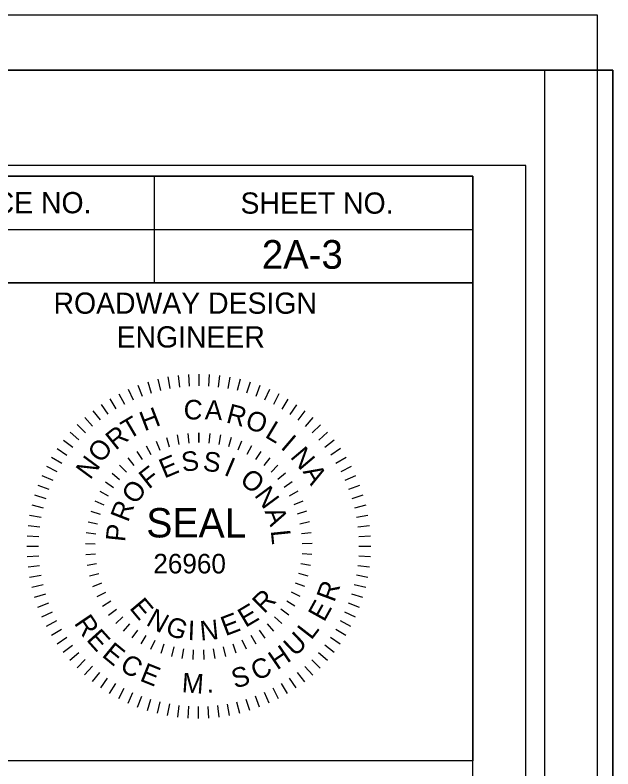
# Model space of a CAD drawing. Extents: x 2294455 to 2294795, y 719276 to 719941.
# Drawn here: x 2294766.36 to 2294794.52, y 719683.27 to 719718.76 of the extents above; entities that cross this region are included whole.
import ezdxf

# ---------------------------------------------------------------- set-up
doc = ezdxf.new("R2010")
doc.units = 0
for name, color, linetype in [('Default', 7, 'Continuous'), ('Old_Level_1', 7, 'Continuous'), ('Old_Level_2', 7, 'Continuous'), ('Sheet Data Field CELL', 7, 'Continuous'), ('Sheet Plan CELL', 7, 'Continuous'), ('Sheet Plot Border Inside CELL', 7, 'Continuous'), ('Sheet Plot Border Outside CELL', 7, 'Continuous'), ('Sheet Typical CELL', 7, 'Continuous')]:
    doc.layers.add(name, color=color, linetype=linetype)

msp = doc.modelspace()

# ---------------------------------------------------------------- linework, layer by layer
at = {"layer": 'Default'}
for p, q in [((2294773.086, 719701.621), (2294773.216, 719701.084)), ((2294773.564, 719701.723), (2294773.662, 719701.18)), ((2294774.047, 719701.796), (2294774.113, 719701.248)), ((2294774.534, 719701.839), (2294774.567, 719701.289)), ((2294775.024, 719701.854), (2294775.023, 719701.302)), ((2294775.513, 719701.839), (2294775.48, 719701.288)), ((2294776, 719701.794), (2294775.934, 719701.246)), ((2294776.484, 719701.72), (2294776.384, 719701.177)), ((2294776.962, 719701.617), (2294776.83, 719701.081)), ((2294772.151, 719701.331), (2294772.347, 719700.814)), ((2294772.613, 719701.49), (2294772.777, 719700.962)), ((2294777.434, 719701.485), (2294777.269, 719700.957)), ((2294777.896, 719701.325), (2294777.699, 719700.809)), ((2294771.259, 719700.93), (2294771.515, 719700.44)), ((2294771.699, 719701.143), (2294771.925, 719700.64)), ((2294778.347, 719701.137), (2294778.121, 719700.634)), ((2294778.787, 719700.923), (2294778.53, 719700.434)), ((2294770.832, 719700.69), (2294771.118, 719700.217)), ((2294779.214, 719700.682), (2294778.927, 719700.21)), ((2294770.027, 719700.135), (2294770.367, 719699.7)), ((2294770.421, 719700.424), (2294770.734, 719699.97)), ((2294779.624, 719700.416), (2294779.31, 719699.962)), ((2294780.017, 719700.126), (2294779.677, 719699.691)), ((2294769.651, 719699.822), (2294770.016, 719699.408)), ((2294780.393, 719699.812), (2294780.027, 719699.399)), ((2294769.294, 719699.487), (2294769.684, 719699.096)), ((2294780.749, 719699.476), (2294780.359, 719699.086)), ((2294768.959, 719699.131), (2294769.371, 719698.764)), ((2294774.506, 719699.068), (2294774.55, 719698.61)), ((2294775.021, 719699.092), (2294775.021, 719698.633)), ((2294775.021, 719698.633), (2294775.021, 719699.092)), ((2294775.537, 719699.067), (2294775.492, 719698.609)), ((2294781.084, 719699.12), (2294780.671, 719698.754)), ((2294768.645, 719698.755), (2294769.079, 719698.415)), ((2294773.008, 719698.701), (2294773.181, 719698.274)), ((2294773.495, 719698.871), (2294773.626, 719698.43)), ((2294773.996, 719698.994), (2294774.083, 719698.542)), ((2294776.047, 719698.992), (2294775.958, 719698.541)), ((2294776.547, 719698.868), (2294776.416, 719698.427)), ((2294777.034, 719698.697), (2294776.86, 719698.27)), ((2294781.397, 719698.743), (2294780.962, 719698.404)), ((2294768.354, 719698.362), (2294768.808, 719698.048)), ((2294772.54, 719698.483), (2294772.753, 719698.076)), ((2294777.502, 719698.479), (2294777.288, 719698.072)), ((2294781.687, 719698.349), (2294781.233, 719698.036)), ((2294772.095, 719698.222), (2294772.346, 719697.837)), ((2294777.946, 719698.217), (2294777.694, 719697.832)), ((2294768.088, 719697.951), (2294768.56, 719697.664)), ((2294771.677, 719697.919), (2294771.965, 719697.56)), ((2294778.364, 719697.913), (2294778.075, 719697.554)), ((2294781.952, 719697.938), (2294781.48, 719697.653)), ((2294767.847, 719697.525), (2294768.336, 719697.268)), ((2294771.291, 719697.577), (2294771.612, 719697.248)), ((2294778.749, 719697.571), (2294778.427, 719697.241)), ((2294782.192, 719697.512), (2294781.703, 719697.255)), ((2294767.633, 719697.085), (2294768.136, 719696.858)), ((2294770.939, 719697.2), (2294771.29, 719696.903)), ((2294779.1, 719697.193), (2294778.748, 719696.896)), ((2294782.405, 719697.071), (2294781.902, 719696.846)), ((2294767.445, 719696.633), (2294767.961, 719696.437)), ((2294770.625, 719696.791), (2294771.004, 719696.528)), ((2294779.413, 719696.783), (2294779.034, 719696.521)), ((2294782.593, 719696.619), (2294782.076, 719696.423)), ((2294770.353, 719696.353), (2294770.755, 719696.128)), ((2294779.684, 719696.345), (2294779.282, 719696.12)), ((2294767.285, 719696.171), (2294767.813, 719696.007)), ((2294770.124, 719695.89), (2294770.546, 719695.706)), ((2294779.913, 719695.881), (2294779.491, 719695.698)), ((2294782.752, 719696.157), (2294782.224, 719695.993)), ((2294767.153, 719695.699), (2294767.689, 719695.568)), ((2294782.883, 719695.685), (2294782.347, 719695.554)), ((2294767.05, 719695.221), (2294767.593, 719695.122)), ((2294769.941, 719695.408), (2294770.379, 719695.266)), ((2294780.095, 719695.399), (2294779.657, 719695.258)), ((2294782.985, 719695.207), (2294782.442, 719695.108)), ((2294769.805, 719694.911), (2294770.254, 719694.811)), ((2294780.23, 719694.901), (2294779.781, 719694.802)), ((2294766.977, 719694.738), (2294767.524, 719694.671)), ((2294783.058, 719694.723), (2294782.51, 719694.657)), ((2294766.932, 719694.251), (2294767.483, 719694.217)), ((2294769.717, 719694.402), (2294770.174, 719694.347)), ((2294780.317, 719694.392), (2294779.86, 719694.338)), ((2294783.102, 719694.236), (2294782.551, 719694.203)), ((2294766.916, 719693.761), (2294767.468, 719693.761)), ((2294769.679, 719693.888), (2294770.139, 719693.876)), ((2294780.354, 719693.878), (2294779.894, 719693.867)), ((2294783.116, 719693.746), (2294782.564, 719693.747)), ((2294769.691, 719693.372), (2294770.15, 719693.405)), ((2294780.341, 719693.362), (2294779.882, 719693.396)), ((2294766.931, 719693.272), (2294767.482, 719693.305)), ((2294783.101, 719693.257), (2294782.55, 719693.291)), ((2294766.975, 719692.785), (2294767.522, 719692.851)), ((2294769.754, 719692.86), (2294770.206, 719692.937)), ((2294779.827, 719692.944), (2294780.281, 719692.867)), ((2294783.056, 719692.77), (2294782.509, 719692.837)), ((2294767.047, 719692.301), (2294767.59, 719692.4)), ((2294769.864, 719692.356), (2294770.308, 719692.476)), ((2294780.166, 719692.346), (2294779.723, 719692.467)), ((2294782.983, 719692.286), (2294782.44, 719692.386)), ((2294767.15, 719691.823), (2294767.686, 719691.954)), ((2294770.023, 719691.865), (2294770.453, 719692.028)), ((2294780.006, 719691.856), (2294779.576, 719692.019)), ((2294782.88, 719691.809), (2294782.344, 719691.94)), ((2294770.229, 719691.393), (2294770.641, 719691.596)), ((2294779.799, 719691.384), (2294779.388, 719691.588)), ((2294767.28, 719691.351), (2294767.809, 719691.515)), ((2294782.748, 719691.336), (2294782.22, 719691.501)), ((2294767.44, 719690.889), (2294767.956, 719691.084)), ((2294770.478, 719690.942), (2294770.87, 719691.183)), ((2294779.549, 719690.933), (2294779.158, 719691.176)), ((2294782.588, 719690.875), (2294782.071, 719691.071)), ((2294767.627, 719690.437), (2294768.131, 719690.662)), ((2294770.771, 719690.516), (2294771.138, 719690.795)), ((2294779.256, 719690.508), (2294778.89, 719690.788)), ((2294782.399, 719690.423), (2294781.896, 719690.649)), ((2294767.84, 719689.996), (2294768.33, 719690.252)), ((2294771.104, 719690.122), (2294771.441, 719690.434)), ((2294778.922, 719690.115), (2294778.586, 719690.428)), ((2294782.185, 719689.983), (2294781.696, 719690.24)), ((2294768.081, 719689.569), (2294768.553, 719689.855)), ((2294771.472, 719689.761), (2294771.778, 719690.106)), ((2294771.874, 719689.438), (2294772.145, 719689.81)), ((2294778.553, 719689.755), (2294778.248, 719690.1)), ((2294781.944, 719689.557), (2294781.472, 719689.843)), ((2294768.346, 719689.159), (2294768.8, 719689.472)), ((2294772.305, 719689.155), (2294772.539, 719689.552)), ((2294777.719, 719689.15), (2294777.485, 719689.547)), ((2294778.15, 719689.432), (2294777.88, 719689.804)), ((2294781.678, 719689.146), (2294781.224, 719689.46)), ((2294768.635, 719688.765), (2294769.07, 719689.104)), ((2294772.762, 719688.915), (2294772.957, 719689.332)), ((2294773.24, 719688.719), (2294773.393, 719689.154)), ((2294776.783, 719688.716), (2294776.631, 719689.151)), ((2294777.261, 719688.911), (2294777.068, 719689.328)), ((2294768.949, 719688.388), (2294769.362, 719688.754)), ((2294773.842, 719689.019), (2294773.731, 719688.572)), ((2294774.24, 719688.472), (2294774.307, 719688.927)), ((2294774.754, 719688.421), (2294774.776, 719688.881)), ((2294775.269, 719688.421), (2294775.248, 719688.881)), ((2294775.783, 719688.471), (2294775.717, 719688.926)), ((2294776.289, 719688.569), (2294776.179, 719689.017)), ((2294781.074, 719688.377), (2294780.662, 719688.743)), ((2294781.388, 719688.753), (2294780.954, 719689.093)), ((2294769.284, 719688.032), (2294769.674, 719688.422)), ((2294780.738, 719688.021), (2294780.349, 719688.412)), ((2294769.639, 719687.696), (2294770.006, 719688.109)), ((2294780.382, 719687.686), (2294780.016, 719688.099)), ((2294770.015, 719687.382), (2294770.356, 719687.816)), ((2294780.006, 719687.373), (2294779.666, 719687.808)), ((2294770.409, 719687.092), (2294770.723, 719687.546)), ((2294779.612, 719687.084), (2294779.298, 719687.538)), ((2294770.819, 719686.826), (2294771.106, 719687.298)), ((2294771.245, 719686.585), (2294771.503, 719687.074)), ((2294778.774, 719686.578), (2294778.518, 719687.067)), ((2294779.201, 719686.818), (2294778.915, 719687.291)), ((2294771.686, 719686.371), (2294771.912, 719686.874)), ((2294772.137, 719686.182), (2294772.334, 719686.699)), ((2294777.882, 719686.177), (2294777.686, 719686.694)), ((2294778.333, 719686.365), (2294778.108, 719686.868)), ((2294772.599, 719686.022), (2294772.764, 719686.55)), ((2294773.071, 719685.891), (2294773.203, 719686.427)), ((2294773.549, 719685.788), (2294773.649, 719686.33)), ((2294774.032, 719685.714), (2294774.099, 719686.262)), ((2294775.985, 719685.712), (2294775.92, 719686.26)), ((2294776.469, 719685.785), (2294776.37, 719686.328)), ((2294776.947, 719685.887), (2294776.816, 719686.423)), ((2294777.419, 719686.018), (2294777.256, 719686.546)), ((2294774.52, 719685.669), (2294774.553, 719686.22)), ((2294775.009, 719685.654), (2294775.009, 719686.206)), ((2294775.498, 719685.668), (2294775.466, 719686.219))]:
    msp.add_line(p, q, dxfattribs=at)
msp.add_lwpolyline([(2294454.524, 719716.169), (2294794.524, 719716.169), (2294794.524, 719496.169), (2294454.524, 719496.169)], close=True, dxfattribs=at)
at = {"layer": 'Old_Level_1'}
msp.add_lwpolyline([(2294747.917, 719676.44), (2294787.924, 719676.44), (2294787.924, 719683.659), (2294747.917, 719683.659)], close=True, dxfattribs=at)
at = {"layer": 'Old_Level_2'}
for p, q in [((2294454.524, 719716.169), (2294794.524, 719716.169)), ((2294794.524, 719716.169), (2294794.524, 719496.169))]:
    msp.add_line(p, q, dxfattribs=at)
at = {"layer": 'Sheet Plan CELL'}
msp.add_lwpolyline([(2294787.924, 719683.659), (2294761.64, 719683.659), (2294761.64, 719706.159), (2294787.924, 719706.159)], dxfattribs=at)
at = {"layer": 'Sheet Plot Border Inside CELL'}
msp.add_lwpolyline([(2294790.424, 719711.679), (2294457.124, 719711.679), (2294457.124, 719500.659), (2294790.424, 719500.659)], close=True, dxfattribs=at)
at = {"layer": 'Sheet Plot Border Outside CELL'}
for points in [[(2294793.79, 719718.758), (2294456.99, 719718.758), (2294456.99, 719498.758), (2294793.79, 719498.758)], [(2294454.524, 719496.169), (2294791.324, 719496.169), (2294791.324, 719716.169), (2294454.524, 719716.169)], [(2294794.524, 719716.169), (2294454.524, 719716.169), (2294454.524, 719496.169), (2294794.524, 719496.169)]]:
    msp.add_lwpolyline(points, close=True, dxfattribs=at)
at = {"layer": 'Sheet Typical CELL'}
for p, q in [((2294772.924, 719711.159), (2294772.924, 719706.159)), ((2294747.914, 719708.659), (2294787.924, 719708.659))]:
    msp.add_line(p, q, dxfattribs=at)
for points in [[(2294787.924, 719711.169), (2294487.924, 719711.169), (2294487.924, 719501.169), (2294787.924, 719501.169)], [(2294747.914, 719711.169), (2294787.924, 719711.169), (2294787.924, 719706.159), (2294747.914, 719706.159)], [(2294787.924, 719706.159), (2294787.924, 719706.159), (2294787.924, 719683.659), (2294787.924, 719683.659)]]:
    msp.add_lwpolyline(points, close=True, dxfattribs=at)

# ---------------------------------------------------------------- texts
at = {"layer": 'Default'}
for s, height, rotation, p in [('C', 0.919, 357.3039, (2294774.286, 719699.747)), ('A', 0.919, 357.3039, (2294775.291, 719699.727)), ('R', 0.919, 345.2946, (2294776.265, 719699.591)), ('H', 0.919, 21.0146, (2294772.456, 719699.157)), ('O', 0.919, 342.2378, (2294777.156, 719699.325)), ('T', 0.919, 30.4466, (2294771.715, 719698.758)), ('L', 0.919, 329.1015, (2294778.091, 719698.915)), ('R', 0.919, 38.6075, (2294771.097, 719698.244)), ('O', 0.919, 51.6643, (2294770.43, 719697.625)), ('I', 0.919, 319.5261, (2294778.832, 719698.38)), ('N', 0.919, 310.2316, (2294779.292, 719697.947)), ('N', 0.919, 53.6237, (2294769.901, 719696.849)), ('E', 0.919, 22.8914, (2294773.397, 719696.936)), ('S', 0.919, 7.5951, (2294774.261, 719697.251)), ('S', 0.919, 352.2989, (2294775.179, 719697.326)), ('I', 0.919, 337.0026, (2294776.157, 719697.127)), ('F', 0.919, 38.1876, (2294772.661, 719696.416)), ('O', 0.919, 321.7064, (2294776.898, 719696.768)), ('A', 0.919, 300.4641, (2294779.898, 719697.267)), ('O', 0.919, 53.4838, (2294772.049, 719695.675)), ('N', 0.919, 306.4101, (2294777.606, 719696.152)), ('R', 0.919, 68.7801, (2294771.684, 719694.85)), ('SEAL', 1.3802, 359.947, (2294772.544, 719694.17)), ('A', 0.919, 291.1139, (2294778.109, 719695.398)), ('P', 0.919, 84.0763, (2294771.544, 719693.938)), ('L', 0.919, 275.8176, (2294778.406, 719694.488)), ('26960', 0.9194, 359.947, (2294772.876, 719692.478)), ('R', 0.919, 69.6194, (2294781.396, 719691.083)), ('R', 0.919, 44.5119, (2294778.093, 719690.547)), ('E', 0.919, 310.0171, (2294771.718, 719690.837)), ('E', 0.919, 60.9466, (2294780.922, 719690.155)), ('E', 0.919, 30.7408, (2294777.217, 719689.907)), ('R', 0.919, 303.882, (2294769.12, 719690.136)), ('N', 0.919, 330.8721, (2294772.49, 719690.07)), ('E', 0.919, 20.7549, (2294776.273, 719689.515)), ('G', 0.919, 339.6384, (2294773.389, 719689.638)), ('I', 0.919, 357.7332, (2294774.484, 719689.342)), ('N', 0.919, 5.3628, (2294775.108, 719689.311)), ('E', 0.919, 311.9538, (2294769.689, 719689.341)), ('L', 0.919, 52.154, (2294780.314, 719689.308)), ('U', 0.919, 43.2714, (2294779.542, 719688.524)), ('E', 0.919, 320.5966, (2294770.413, 719688.591)), ('H', 0.919, 34.3888, (2294778.704, 719687.904)), ('C', 0.919, 329.2691, (2294771.241, 719687.958)), ('C', 0.919, 25.5662, (2294777.744, 719687.398)), ('E', 0.919, 338.2416, (2294772.195, 719687.439)), ('S', 0.919, 16.5636, (2294776.715, 719687.049)), ('M', 0.919, 356.0369, (2294774.199, 719686.883)), ('.', 0.919, 3.7793, (2294775.399, 719686.853))]:
    msp.add_text(s, height=height, rotation=rotation, dxfattribs=at).set_placement(p)
at = {"layer": 'Sheet Data Field CELL'}
msp.add_text('2A-3', height=1.35, dxfattribs=at).set_placement((2294777.988, 719706.817))
at = {"layer": 'Sheet Plan CELL'}
for s, height, p in [('ROADWAY DESIGN', 1.00002, (2294768.176, 719704.699)), ('ENGINEER', 1, (2294771.146, 719703.109))]:
    msp.add_text(s, height=height, dxfattribs=at).set_placement(p)
at = {"layer": 'Sheet Typical CELL'}
for s, height, p in [('PROJECT REFERENCE NO.', 1.00002, (2294752.354, 719709.429)), ('SHEET NO.', 1, (2294776.984, 719709.409))]:
    msp.add_text(s, height=height, dxfattribs=at).set_placement(p)

doc.saveas('drawing.dxf')
